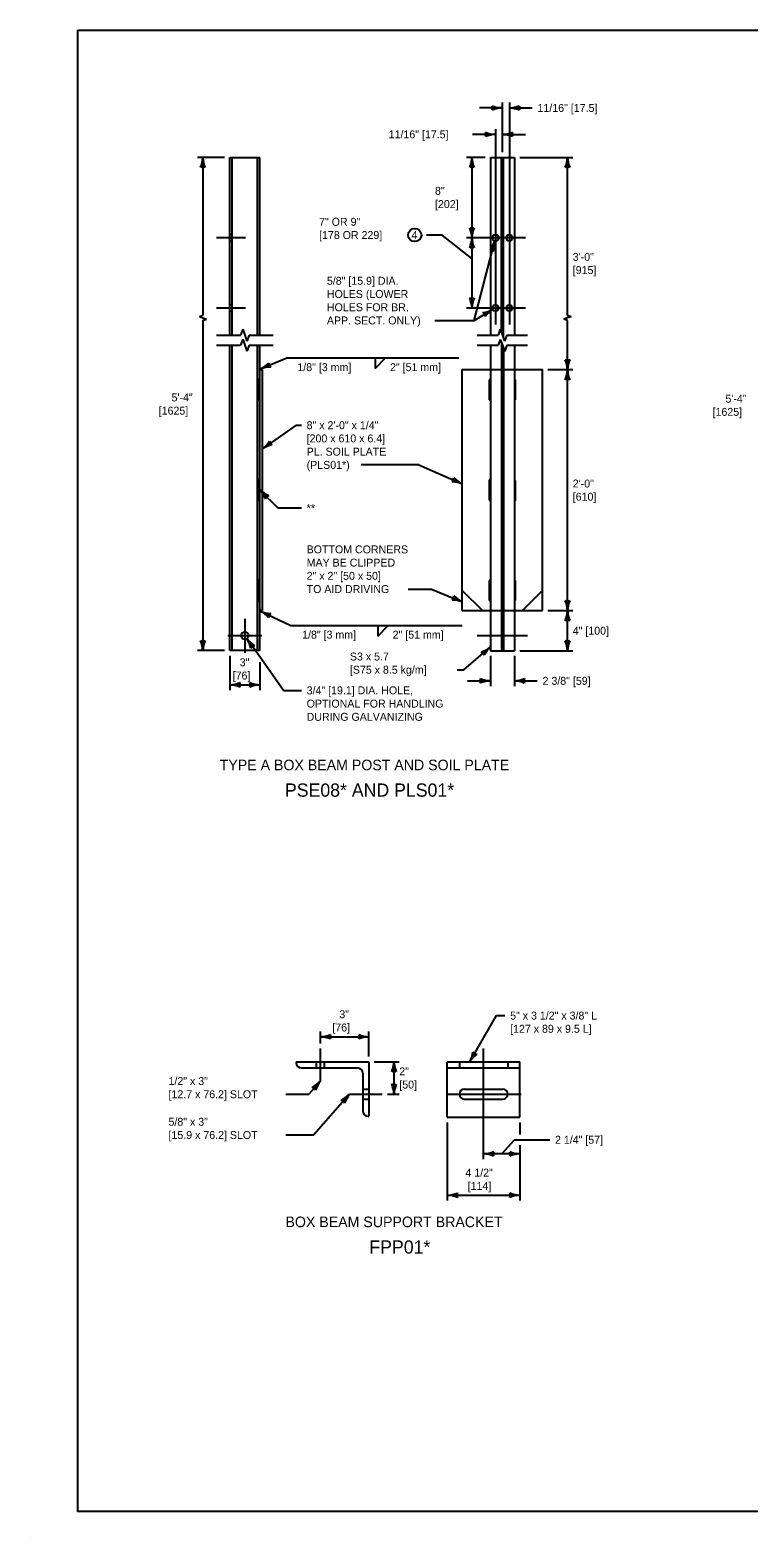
# Model space of a CAD drawing. Extents: x 49991.4 to 50021, y 49987.6 to 50011.4.
# Drawn here: x 49999.02 to 50004.46, y 49987.6 to 49999 of the extents above; entities that cross this region are included whole.
import ezdxf

# ---------------------------------------------------------------- set-up
doc = ezdxf.new("R2010")
doc.units = 0
for name, color, linetype in [('Level 1', 7, 'Continuous'), ('Level 2', 7, 'Continuous'), ('Level 3', 7, 'Continuous'), ('Level 4', 7, 'Continuous'), ('Level 5', 7, 'Continuous'), ('Level 6', 7, 'Continuous')]:
    doc.layers.add(name, color=color, linetype=linetype)

msp = doc.modelspace()

# ---------------------------------------------------------------- linework, layer by layer
at = {"layer": 'Level 1'}
for p, q in [((50000.533, 49996.693), (50000.533, 49998.037)), ((50000.533, 49998.037), (50000.761, 49998.037)), ((50000.552, 49996.693), (50000.552, 49998.037)), ((50000.742, 49996.693), (50000.742, 49998.037)), ((50000.761, 49996.693), (50000.761, 49998.037)), ((50002.503, 49998.037), (50002.684, 49998.037)), ((50002.503, 49998.037), (50002.503, 49996.692)), ((50002.684, 49998.037), (50002.684, 49996.692)), ((50000.533, 49994.308), (50000.533, 49996.617)), ((50000.552, 49994.308), (50000.552, 49996.617)), ((50000.742, 49994.308), (50000.742, 49996.617)), ((50000.761, 49994.308), (50000.761, 49996.617)), ((50002.503, 49996.616), (50002.503, 49994.307)), ((50002.684, 49996.616), (50002.684, 49994.307)), ((50000.761, 49996.357), (50000.751, 49996.357)), ((50000.751, 49996.357), (50000.751, 49996.205)), ((50000.78, 49996.433), (50000.761, 49996.433)), ((50000.761, 49996.205), (50000.761, 49996.357)), ((50000.78, 49994.611), (50000.78, 49996.433)), ((50002.29, 49994.61), (50002.29, 49996.432)), ((50002.29, 49996.432), (50002.503, 49996.432)), ((50002.503, 49996.356), (50002.494, 49996.356)), ((50002.494, 49996.356), (50002.494, 49996.204)), ((50002.503, 49996.204), (50002.503, 49996.356)), ((50002.684, 49996.432), (50002.897, 49996.432)), ((50002.693, 49996.355), (50002.684, 49996.355)), ((50002.684, 49996.355), (50002.684, 49996.203)), ((50002.693, 49996.203), (50002.693, 49996.355)), ((50002.897, 49994.61), (50002.897, 49996.432)), ((50000.751, 49996.205), (50000.761, 49996.205)), ((50002.494, 49996.204), (50002.503, 49996.204)), ((50002.684, 49996.203), (50002.693, 49996.203)), ((50000.761, 49995.598), (50000.751, 49995.598)), ((50000.751, 49995.598), (50000.751, 49995.446)), ((50000.761, 49995.446), (50000.761, 49995.598)), ((50002.503, 49995.598), (50002.494, 49995.598)), ((50002.494, 49995.598), (50002.494, 49995.446)), ((50002.503, 49995.446), (50002.503, 49995.598)), ((50002.693, 49995.593), (50002.684, 49995.593)), ((50002.684, 49995.593), (50002.684, 49995.441)), ((50002.693, 49995.441), (50002.693, 49995.593)), ((50000.751, 49995.446), (50000.761, 49995.446)), ((50002.494, 49995.446), (50002.503, 49995.446)), ((50002.684, 49995.441), (50002.693, 49995.441)), ((50000.761, 49994.837), (50000.751, 49994.837)), ((50000.751, 49994.837), (50000.751, 49994.685)), ((50000.761, 49994.685), (50000.761, 49994.837)), ((50002.503, 49994.838), (50002.494, 49994.838)), ((50002.494, 49994.838), (50002.494, 49994.686)), ((50002.503, 49994.686), (50002.503, 49994.838)), ((50002.693, 49994.838), (50002.684, 49994.838)), ((50002.684, 49994.838), (50002.684, 49994.686)), ((50002.693, 49994.686), (50002.693, 49994.838)), ((50000.751, 49994.685), (50000.761, 49994.685)), ((50002.494, 49994.686), (50002.503, 49994.686)), ((50002.684, 49994.686), (50002.693, 49994.686)), ((50000.78, 49994.611), (50000.761, 49994.611)), ((50002.29, 49994.61), (50002.503, 49994.61)), ((50002.684, 49994.61), (50002.897, 49994.61)), ((50000.761, 49994.308), (50000.533, 49994.308)), ((50002.503, 49994.307), (50002.684, 49994.307)), ((50001.035, 49991.198), (50001.584, 49991.198)), ((50001.035, 49991.198), (50001.035, 49991.192)), ((50001.075, 49991.152), (50001.498, 49991.152)), ((50001.538, 49991.112), (50001.538, 49990.827)), ((50001.584, 49991.198), (50001.584, 49990.787)), ((50002.177, 49990.779), (50002.177, 49991.198)), ((50002.177, 49991.198), (50002.725, 49991.198)), ((50002.177, 49991.152), (50002.725, 49991.152)), ((50002.725, 49990.779), (50002.725, 49991.198)), ((50002.306, 49990.992), (50002.596, 49990.992)), ((50002.306, 49990.916), (50002.596, 49990.916)), ((50001.578, 49990.787), (50001.584, 49990.787)), ((50002.177, 49990.779), (50002.725, 49990.779)), ((49999.024, 49987.599), (49999.024, 49987.599))]:
    msp.add_line(p, q, dxfattribs=at)
msp.add_lwpolyline([(49999.384, 49998.999), (50016.75, 49998.999), (50016.75, 49987.799), (49999.384, 49987.799)], close=True, dxfattribs=at)
for points in [[(50000.761, 49996.442), (50000.761, 49996.433), (50000.771, 49996.433), (50000.761, 49996.442)], [(50000.761, 49994.601), (50000.761, 49994.611), (50000.771, 49994.611), (50000.761, 49994.601)]]:
    msp.add_lwpolyline(points, dxfattribs=at)
for centre, radius in [((50002.541, 49997.429), 0.0237), ((50002.646, 49997.429), 0.0237), ((50002.541, 49996.898), 0.0237), ((50002.646, 49996.898), 0.0237), ((50000.647, 49994.421), 0.0285)]:
    msp.add_circle(centre, radius, dxfattribs=at)
for centre, radius, start, end in [((50001.075, 49991.192), 0.04, 180, 270), ((50001.498, 49991.112), 0.04, 0, 90), ((50002.306, 49990.954), 0.038, 90.4301, 269.5699), ((50002.596, 49990.954), 0.038, 270.4301, 89.5699), ((50001.578, 49990.827), 0.04, 180, 270)]:
    msp.add_arc(centre, radius, start, end, dxfattribs=at)
at = {"layer": 'Level 2'}
msp.add_circle((50001.931, 49997.45), 0.05, dxfattribs=at)
at = {"layer": 'Level 3'}
for p, q in [((50002.593, 49998.411), (50002.42, 49998.411)), ((50002.593, 49998.077), (50002.593, 49998.451)), ((50002.646, 49998.411), (50002.819, 49998.411)), ((50002.541, 49998.211), (50002.368, 49998.211)), ((50002.593, 49998.211), (50002.767, 49998.211)), ((50000.493, 49998.037), (50000.29, 49998.037)), ((50000.33, 49998.037), (50000.33, 49996.844)), ((50002.463, 49998.037), (50002.323, 49998.037)), ((50002.363, 49998.037), (50002.363, 49997.429)), ((50002.724, 49998.037), (50003.125, 49998.037)), ((50003.085, 49996.842), (50003.085, 49998.037)), ((50002.137, 49997.45), (50002.021, 49997.45)), ((50002.363, 49997.272), (50002.137, 49997.45)), ((50002.363, 49997.429), (50002.363, 49996.898)), ((50002.38, 49996.804), (50002.535, 49997.406)), ((50000.303, 49996.834), (50000.33, 49996.844)), ((50000.303, 49996.834), (50000.33, 49996.824)), ((50000.33, 49996.824), (50000.358, 49996.815)), ((50000.33, 49996.805), (50000.358, 49996.815)), ((50000.33, 49996.805), (50000.33, 49994.308)), ((50002.083, 49996.804), (50002.38, 49996.804)), ((50002.38, 49996.804), (50002.521, 49996.886)), ((50003.085, 49996.823), (50003.057, 49996.813)), ((50003.085, 49996.803), (50003.057, 49996.813)), ((50003.112, 49996.832), (50003.085, 49996.842)), ((50003.112, 49996.832), (50003.085, 49996.823)), ((50003.085, 49996.432), (50003.085, 49996.803)), ((50000.766, 49996.438), (50000.963, 49996.521)), ((50000.963, 49996.521), (50002.265, 49996.521)), ((50001.631, 49996.521), (50001.631, 49996.441)), ((50001.631, 49996.441), (50001.711, 49996.521)), ((50002.937, 49996.432), (50003.125, 49996.432)), ((50003.085, 49994.61), (50003.085, 49996.432)), ((50001.035, 49996.012), (50000.78, 49995.833)), ((50001.035, 49996.012), (50001.074, 49996.012)), ((50001.963, 49995.712), (50001.526, 49995.712)), ((50001.963, 49995.712), (50002.29, 49995.569)), ((50000.761, 49995.522), (50000.898, 49995.385)), ((50001.074, 49995.385), (50000.898, 49995.385)), ((50001.882, 49994.773), (50002.057, 49994.773)), ((50002.057, 49994.773), (50002.29, 49994.676)), ((50000.766, 49994.606), (50000.994, 49994.498)), ((50002.937, 49994.61), (50003.125, 49994.61)), ((50003.085, 49994.307), (50003.085, 49994.61)), ((50000.994, 49994.498), (50002.289, 49994.498)), ((50001.651, 49994.498), (50001.651, 49994.418)), ((50001.651, 49994.418), (50001.731, 49994.498)), ((50000.493, 49994.308), (50000.29, 49994.308)), ((50000.938, 49994.007), (50000.664, 49994.397)), ((50002.301, 49994.163), (50002.503, 49994.335)), ((50002.724, 49994.307), (50003.125, 49994.307)), ((50000.533, 49994.268), (50000.533, 49994.009)), ((50000.761, 49994.219), (50000.761, 49994.009)), ((50002.503, 49994.267), (50002.503, 49994.039)), ((50002.684, 49994.267), (50002.684, 49994.039)), ((50002.252, 49994.163), (50002.301, 49994.163)), ((50002.33, 49994.079), (50002.503, 49994.079)), ((50002.684, 49994.079), (50002.857, 49994.079)), ((50000.533, 49994.049), (50000.761, 49994.049)), ((50000.938, 49994.007), (50001.074, 49994.007))]:
    msp.add_line(p, q, dxfattribs=at)
for points in [[(50002.347, 49991.198), (50002.549, 49991.548)], [(50002.549, 49991.548), (50002.612, 49991.548)], [(50001.218, 49991.338), (50001.218, 49991.428)], [(50001.218, 49991.388), (50001.584, 49991.388)], [(50001.584, 49991.238), (50001.584, 49991.428)], [(50001.624, 49991.198), (50001.814, 49991.198)], [(50001.774, 49991.198), (50001.774, 49990.954)], [(50001.218, 49991.052), (50001.131, 49990.953)], [(50000.957, 49990.953), (50001.131, 49990.953)], [(50001.438, 49990.954), (50001.168, 49990.645)], [(50001.724, 49990.954), (50001.814, 49990.954)], [(50000.957, 49990.645), (50001.168, 49990.645)], [(50002.177, 49990.739), (50002.177, 49990.15)], [(50002.725, 49990.739), (50002.725, 49990.649)], [(50002.588, 49990.502), (50002.684, 49990.609), (50002.725, 49990.609)], [(50002.725, 49990.609), (50002.951, 49990.609)], [(50002.725, 49990.569), (50002.725, 49990.15)], [(50002.725, 49990.502), (50002.451, 49990.502)], [(50002.177, 49990.19), (50002.725, 49990.19)]]:
    msp.add_lwpolyline(points, dxfattribs=at)
for centre, radius, start, end in [((50002.465, 49998.411), 0.0548, 342.1388, 17.8612), ((50002.605, 49998.643), 0.233, 247.9228, 267.1727), ((50002.603, 49998.189), 0.222, 92.3605, 112.544), ((50002.637, 49998.633), 0.222, 272.3605, 292.544), ((50002.634, 49998.178), 0.233, 67.9228, 87.1727), ((50002.774, 49998.411), 0.0548, 162.1388, 197.8612), ((50002.55, 49998.433), 0.222, 247.456, 267.6395), ((50002.413, 49998.211), 0.0548, 342.1388, 17.8612), ((50002.553, 49997.978), 0.233, 92.8273, 112.0772), ((50002.582, 49998.443), 0.233, 272.8273, 292.0772), ((50002.584, 49997.989), 0.222, 67.456, 87.6395), ((50002.722, 49998.211), 0.0548, 162.1388, 197.8612), ((50000.097, 49998.048), 0.233, 337.9228, 357.1727), ((50000.33, 49997.908), 0.0548, 72.1388, 107.8612), ((50000.552, 49998.046), 0.222, 182.3605, 202.544), ((50002.141, 49998.046), 0.222, 337.456, 357.6395), ((50002.363, 49997.908), 0.0548, 72.1388, 107.8612), ((50002.596, 49998.048), 0.233, 182.8273, 202.0772), ((50002.863, 49998.046), 0.222, 337.456, 357.6395), ((50003.085, 49997.908), 0.0548, 72.1388, 107.8612), ((50003.318, 49998.048), 0.233, 182.8273, 202.0772), ((50002.363, 49997.558), 0.0548, 252.1388, 287.8612), ((50002.131, 49997.418), 0.233, 2.8273, 22.0772), ((50002.585, 49997.42), 0.222, 157.456, 177.6395), ((50002.141, 49997.439), 0.222, 337.456, 357.6395), ((50002.596, 49997.441), 0.233, 182.8273, 202.0772), ((50002.323, 49997.471), 0.222, 322.8586, 343.0421), ((50002.763, 49997.359), 0.233, 168.2299, 187.4798), ((50002.363, 49997.301), 0.0548, 72.1388, 107.8612), ((50002.503, 49997.282), 0.0548, 57.5414, 93.2638), ((50002.363, 49997.026), 0.0548, 252.1388, 287.8612), ((50002.131, 49996.887), 0.233, 2.8273, 22.0772), ((50002.585, 49996.889), 0.222, 157.456, 177.6395), ((50002.421, 49997.085), 0.222, 276.5189, 296.7024), ((50002.409, 49996.824), 0.0548, 11.2017, 46.924), ((50002.644, 49996.688), 0.233, 121.8902, 141.14), ((50000.671, 49996.639), 0.222, 295.2219, 315.4054), ((50000.884, 49996.487), 0.0548, 185.0003, 220.7226), ((50003.085, 49996.56), 0.0548, 252.1388, 287.8612), ((50002.852, 49996.42), 0.233, 2.8273, 22.0772), ((50003.307, 49996.423), 0.222, 157.456, 177.6395), ((50000.846, 49996.219), 0.233, 90.7843, 110.0341), ((50002.863, 49996.441), 0.222, 337.456, 357.6395), ((50003.085, 49996.304), 0.0548, 72.1388, 107.8612), ((50003.318, 49996.443), 0.233, 182.8273, 202.0772), ((50000.637, 49996.017), 0.233, 307.8646, 327.1145), ((50000.885, 49995.907), 0.0548, 197.1761, 232.8985), ((50000.9, 49995.646), 0.222, 102.4933, 122.6768), ((50002.172, 49995.62), 0.0548, 318.565, 354.2874), ((50002.209, 49995.362), 0.222, 68.7867, 88.9702), ((50002.393, 49995.777), 0.233, 224.349, 243.5989), ((50000.598, 49995.371), 0.222, 22.456, 42.6395), ((50000.918, 49995.695), 0.233, 227.8273, 247.0772), ((50000.852, 49995.431), 0.0548, 117.1388, 152.8612), ((50002.172, 49994.725), 0.0548, 319.5112, 355.2336), ((50002.211, 49994.457), 0.233, 70.1997, 89.4496), ((50002.384, 49994.878), 0.222, 224.8284, 245.0119), ((50003.085, 49994.738), 0.0548, 252.1388, 287.8612), ((50002.852, 49994.599), 0.233, 2.8273, 22.0772), ((50003.307, 49994.601), 0.222, 157.456, 177.6395), ((50000.662, 49994.41), 0.222, 42.0086, 62.1921), ((50000.856, 49994.821), 0.233, 247.3799, 266.6298), ((50000.882, 49994.551), 0.0548, 136.6914, 172.4138), ((50002.863, 49994.619), 0.222, 337.456, 357.6395), ((50003.085, 49994.482), 0.0548, 72.1388, 107.8612), ((50003.318, 49994.622), 0.233, 182.8273, 202.0772), ((50000.108, 49994.298), 0.222, 2.3605, 22.544), ((50000.33, 49994.436), 0.0548, 252.1388, 287.8612), ((50000.563, 49994.296), 0.233, 157.9228, 177.1727), ((50000.475, 49994.28), 0.222, 11.7099, 31.8934), ((50000.849, 49994.538), 0.233, 217.0812, 236.331), ((50000.736, 49994.291), 0.0548, 106.3927, 142.1151), ((50002.367, 49994.51), 0.222, 287.6936, 307.8771), ((50002.405, 49994.252), 0.0548, 22.3764, 58.0988), ((50002.662, 49994.164), 0.233, 133.0649, 152.3148), ((50003.085, 49994.435), 0.0548, 252.1388, 287.8612), ((50002.852, 49994.295), 0.233, 2.8273, 22.0772), ((50003.307, 49994.297), 0.222, 157.456, 177.6395), ((50000.522, 49994.282), 0.233, 272.8273, 292.0772), ((50000.662, 49994.049), 0.0548, 162.1388, 197.8612), ((50000.77, 49994.271), 0.222, 247.456, 267.6395), ((50000.633, 49994.049), 0.0548, 342.1388, 17.8612), ((50002.513, 49994.302), 0.222, 247.456, 267.6395), ((50002.375, 49994.079), 0.0548, 342.1388, 17.8612), ((50002.515, 49993.847), 0.233, 92.8273, 112.0772), ((50002.672, 49994.312), 0.233, 272.8273, 292.0772), ((50002.674, 49993.857), 0.222, 67.456, 87.6395), ((50002.812, 49994.079), 0.0548, 162.1388, 197.8612), ((50000.524, 49993.827), 0.222, 67.456, 87.6395), ((50000.773, 49993.816), 0.233, 92.8273, 112.0772), ((50001.207, 49991.621), 0.233, 272.8273, 292.0772), ((50001.209, 49991.166), 0.222, 67.456, 87.6395), ((50001.347, 49991.388), 0.0548, 162.1388, 197.8612), ((50001.593, 49991.61), 0.222, 247.456, 267.6395), ((50001.456, 49991.388), 0.0548, 342.1388, 17.8612), ((50001.595, 49991.155), 0.233, 92.8273, 112.0772), ((50002.14, 49991.304), 0.233, 332.8629, 352.1127), ((50002.535, 49991.079), 0.222, 127.4916, 147.6751), ((50002.411, 49991.309), 0.0548, 222.1744, 257.8968), ((50001.552, 49991.207), 0.222, 337.456, 357.6395), ((50001.774, 49991.07), 0.0548, 72.1388, 107.8612), ((50002.007, 49991.21), 0.233, 182.8273, 202.0772), ((50001.057, 49991.205), 0.222, 296.319, 316.5025), ((50001.134, 49990.956), 0.0548, 31.0018, 66.7242), ((50001.401, 49990.908), 0.233, 141.6903, 160.9401), ((50001.774, 49991.082), 0.0548, 252.1388, 287.8612), ((50001.541, 49990.943), 0.233, 2.8273, 22.0772), ((50001.996, 49990.945), 0.222, 157.456, 177.6395), ((50001.277, 49991.107), 0.222, 296.3233, 316.5068), ((50001.354, 49990.858), 0.0548, 31.0061, 66.7284), ((50001.621, 49990.81), 0.233, 141.6946, 160.9444), ((50002.44, 49990.735), 0.233, 272.8273, 292.0772), ((50002.442, 49990.28), 0.222, 67.456, 87.6395), ((50002.579, 49990.502), 0.0548, 162.1388, 197.8612), ((50002.735, 49990.724), 0.222, 247.456, 267.6395), ((50002.597, 49990.502), 0.0548, 342.1388, 17.8612), ((50002.737, 49990.27), 0.233, 92.8273, 112.0772), ((50002.165, 49990.422), 0.233, 272.8273, 292.0772), ((50002.168, 49989.968), 0.222, 67.456, 87.6395), ((50002.305, 49990.19), 0.0548, 162.1388, 197.8612), ((50002.735, 49990.412), 0.222, 247.456, 267.6395), ((50002.597, 49990.19), 0.0548, 342.1388, 17.8612), ((50002.737, 49989.957), 0.233, 92.8273, 112.0772)]:
    msp.add_arc(centre, radius, start, end, dxfattribs=at)
at = {"layer": 'Level 4'}
for p, q in [((50002.586, 49996.713), (50002.586, 49998.037)), ((50002.601, 49996.672), (50002.601, 49998.037)), ((50000.552, 49997.453), (50000.533, 49997.453)), ((50000.552, 49997.406), (50000.533, 49997.406)), ((50000.552, 49996.922), (50000.533, 49996.922)), ((50000.552, 49996.874), (50000.533, 49996.874)), ((50002.586, 49996.636), (50002.586, 49994.307)), ((50002.601, 49996.596), (50002.601, 49994.307)), ((50002.503, 49996.432), (50002.684, 49996.432)), ((50002.29, 49994.762), (50002.442, 49994.61)), ((50002.745, 49994.61), (50002.897, 49994.762)), ((50002.503, 49994.61), (50002.684, 49994.61)), ((50002.586, 49994.449), (50002.601, 49994.449)), ((50002.586, 49994.392), (50002.601, 49994.392)), ((50001.188, 49991.152), (50001.188, 49991.198)), ((50001.249, 49991.152), (50001.249, 49991.198)), ((50002.268, 49991.198), (50002.268, 49991.152)), ((50002.634, 49991.198), (50002.634, 49991.152)), ((50001.538, 49990.992), (50001.584, 49990.992)), ((50001.538, 49990.916), (50001.584, 49990.916))]:
    msp.add_line(p, q, dxfattribs=at)
at = {"layer": 'Level 5'}
for p, q in [((50002.646, 49998.451), (50002.646, 49996.774)), ((50002.541, 49998.251), (50002.541, 49996.774)), ((50000.652, 49997.429), (50000.433, 49997.429)), ((50002.769, 49997.429), (50002.323, 49997.429)), ((50000.652, 49996.898), (50000.433, 49996.898)), ((50002.769, 49996.898), (50002.323, 49996.898)), ((50000.647, 49994.549), (50000.647, 49994.292)), ((50000.519, 49994.421), (50000.776, 49994.421)), ((50002.403, 49994.421), (50002.784, 49994.421)), ((50002.451, 49990.462), (50002.451, 49991.298)), ((50002.168, 49990.954), (50002.734, 49990.954))]:
    msp.add_line(p, q, dxfattribs=at)
for points in [[(50001.218, 49991.052), (50001.218, 49991.298)], [(50001.438, 49990.954), (50001.684, 49990.954)]]:
    msp.add_lwpolyline(points, dxfattribs=at)
at = {"layer": 'Level 6'}
for p, q in [((50000.433, 49996.693), (50000.615, 49996.693)), ((50000.631, 49996.739), (50000.615, 49996.693)), ((50000.631, 49996.739), (50000.647, 49996.693)), ((50000.647, 49996.693), (50000.663, 49996.648)), ((50000.68, 49996.693), (50000.663, 49996.648)), ((50000.68, 49996.693), (50000.861, 49996.693)), ((50002.403, 49996.692), (50002.561, 49996.692)), ((50002.577, 49996.738), (50002.561, 49996.692)), ((50002.577, 49996.738), (50002.593, 49996.692)), ((50002.593, 49996.692), (50002.61, 49996.647)), ((50002.626, 49996.692), (50002.61, 49996.647)), ((50002.626, 49996.692), (50002.784, 49996.692)), ((50000.433, 49996.617), (50000.615, 49996.617)), ((50000.631, 49996.662), (50000.615, 49996.617)), ((50000.631, 49996.662), (50000.647, 49996.617)), ((50000.647, 49996.617), (50000.663, 49996.571)), ((50000.68, 49996.617), (50000.663, 49996.571)), ((50000.68, 49996.617), (50000.861, 49996.617)), ((50002.403, 49996.616), (50002.561, 49996.616)), ((50002.577, 49996.661), (50002.561, 49996.616)), ((50002.577, 49996.661), (50002.593, 49996.616)), ((50002.593, 49996.616), (50002.61, 49996.57)), ((50002.626, 49996.616), (50002.61, 49996.57)), ((50002.626, 49996.616), (50002.784, 49996.616))]:
    msp.add_line(p, q, dxfattribs=at)

# ---------------------------------------------------------------- texts
at = {"layer": 'Level 2'}
for s, p in [('11/16" [17.5]', (50002.859, 49998.381)), ('11/16" [17.5]', (50001.734, 49998.181)), ('8"', (50002.084, 49997.754)), ('[202]', (50002.084, 49997.654)), ('5\'-4"', (50000.093, 49996.192)), ('5\'-4"', (50004.279, 49996.183)), ('[1625]', (49999.996, 49996.092)), ('[1625]', (50004.182, 49996.083))]:
    msp.add_text(s, height=0.06, rotation=360, dxfattribs=at).set_placement(p)
for s, height, p in [('7" OR 9"', 0.06, (50001.208, 49997.52)), ('[178 OR 229]', 0.06, (50001.208, 49997.42)), ('4', 0.06, (50001.907, 49997.42)), ('3\'-0"', 0.06, (50003.125, 49997.255)), ('[915]', 0.06, (50003.125, 49997.155)), ('5/8" [15.9] DIA.', 0.06, (50001.267, 49997.074)), ('HOLES (LOWER', 0.06, (50001.267, 49996.974)), ('HOLES FOR BR.', 0.06, (50001.267, 49996.874)), ('APP. SECT. ONLY)', 0.06, (50001.267, 49996.774)), ('1/8" [3 mm]', 0.06, (50001.044, 49996.421)), ('2" [51 mm]', 0.06, (50001.744, 49996.421)), ('8" x 2\'-0" x 1/4" ', 0.06, (50001.114, 49995.982)), ('[200 x 610 x 6.4]', 0.06, (50001.114, 49995.882)), ('PL. SOIL PLATE', 0.06, (50001.114, 49995.782)), ('(PLS01*)', 0.06, (50001.114, 49995.682)), ('2\'-0"', 0.06, (50003.125, 49995.541)), ('[610]', 0.06, (50003.125, 49995.441)), ('**', 0.06, (50001.114, 49995.355)), ('BOTTOM CORNERS', 0.06, (50001.114, 49995.043)), ('MAY BE CLIPPED', 0.06, (50001.114, 49994.943)), ('2" x 2" [50 x 50]', 0.06, (50001.114, 49994.843)), ('TO AID DRIVING', 0.06, (50001.114, 49994.743)), ('1/8" [3 mm]', 0.06, (50001.08, 49994.398)), ('2" [51 mm]', 0.06, (50001.764, 49994.398)), ('4" [100]', 0.06, (50003.125, 49994.428)), ('S3 x 5.7', 0.06, (50001.441, 49994.233)), ('3"', 0.06, (50000.608, 49994.189)), ('[S75 x 8.5 kg/m]', 0.06, (50001.441, 49994.133)), ('[76]', 0.06, (50000.555, 49994.089)), ('2 3/8" [59]', 0.06, (50002.897, 49994.049)), ('3/4" [19.1] DIA. HOLE,', 0.06, (50001.114, 49993.977)), ('OPTIONAL FOR HANDLING', 0.06, (50001.114, 49993.877)), ('DURING GALVANIZING', 0.06, (50001.114, 49993.777)), ('TYPE A BOX BEAM POST AND SOIL PLATE', 0.08, (50000.457, 49993.403)), ('PSE08* AND PLS01*', 0.1, (50000.95, 49993.203)), ('3"', 0.06, (50001.361, 49991.528)), ('5" x 3 1/2" x 3/8" L', 0.06, (50002.652, 49991.518)), ('[76]', 0.06, (50001.308, 49991.428)), ('[127 x 89 x 9.5 L]', 0.06, (50002.652, 49991.418)), ('2"', 0.06, (50001.814, 49991.096)), ('1/2" x 3"', 0.06, (50000.07, 49991.023)), ('[12.7 x 76.2] SLOT', 0.06, (50000.07, 49990.923)), ('[50]', 0.06, (50001.814, 49990.996)), ('5/8" x 3"', 0.06, (50000.07, 49990.715)), ('[15.9 x 76.2] SLOT', 0.06, (50000.07, 49990.615)), ('2 1/4" [57]', 0.06, (50002.991, 49990.579)), ('4 1/2"', 0.06, (50002.314, 49990.33)), ('[114]', 0.06, (50002.331, 49990.23)), ('BOX BEAM SUPPORT BRACKET', 0.08, (50000.954, 49989.948)), ('FPP01*', 0.1, (50001.588, 49989.748))]:
    msp.add_text(s, height=height, dxfattribs=at).set_placement(p)

doc.saveas('drawing.dxf')
